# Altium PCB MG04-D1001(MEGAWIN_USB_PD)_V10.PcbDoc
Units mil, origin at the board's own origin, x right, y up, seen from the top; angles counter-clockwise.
Board outline 2047.24 x 1181.1 mil, 2 copper layers (Top Layer, Bottom Layer); 67 components, 68 nets, 243 pads, 62 vias.
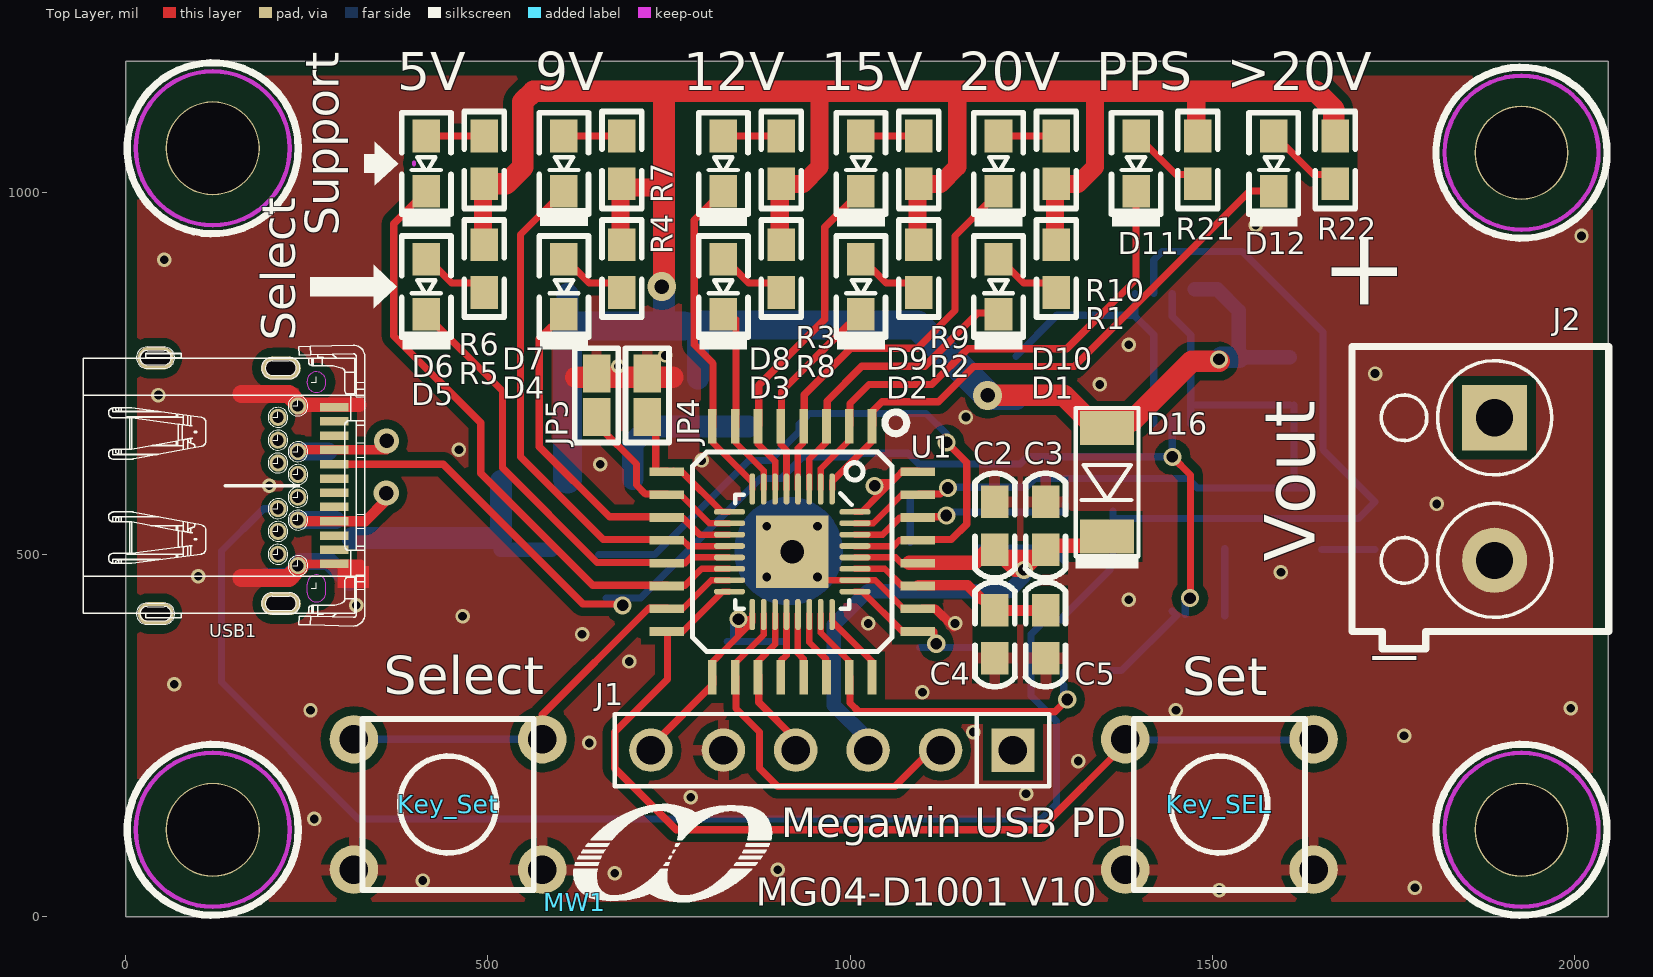
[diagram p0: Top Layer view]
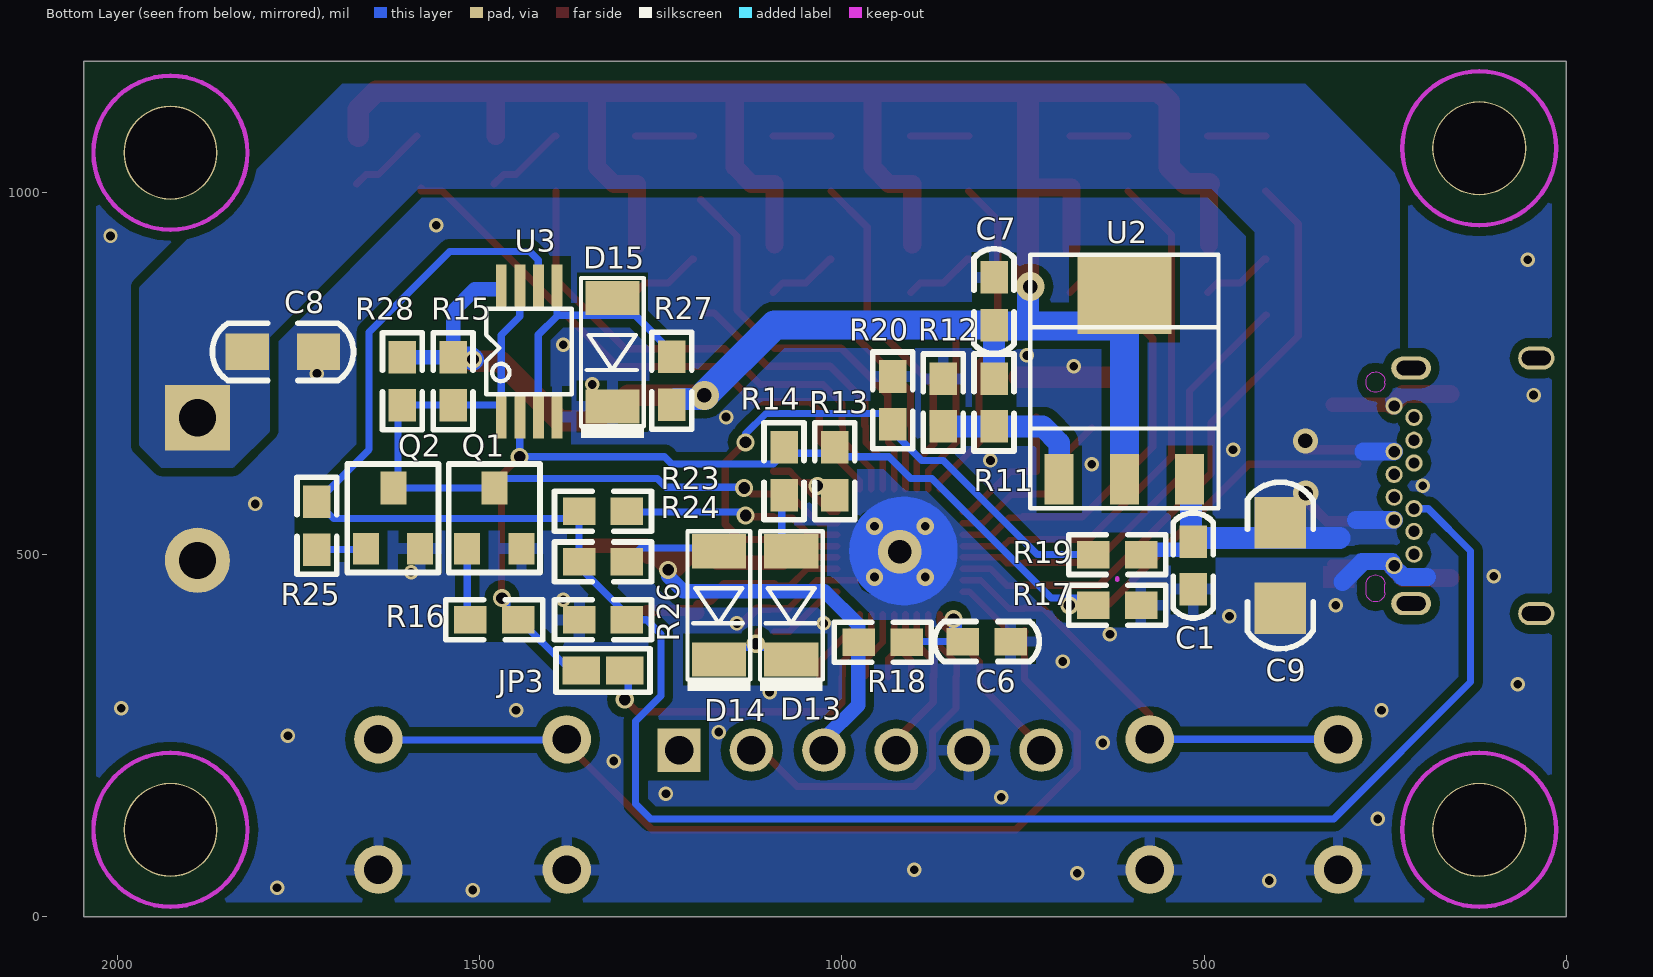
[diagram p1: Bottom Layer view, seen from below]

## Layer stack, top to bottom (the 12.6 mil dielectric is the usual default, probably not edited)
Top Layer: signal copper 1.4
Dielectric: dielectric 12.6, FR-4, Dk 4.8
Bottom Layer: signal copper 1.4

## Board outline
0,0 2047.24,0 2047.24,1181.1 0,1181.1

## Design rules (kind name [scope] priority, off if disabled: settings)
Clearance 15 [All] p1 off: gap=15
Clearance 12 [All] p2 off: gap=12
Clearance 6 [All] p3: gap=6
HoleSize [All] p1: absolutevalues=TRUE maxlimit=300 minlimit=1 maxpercent=80.000 minpercent=20.000
PolygonConnect J2 [(InComponent('J2'))] p1: connectstyle=Direct reliefconductorwidth=10 reliefentries=4 polygonreliefangle="90 Angle"
PolygonConnect C9 [(InComponent('C9'))] p2: connectstyle=Direct reliefconductorwidth=10 reliefentries=4 polygonreliefangle="90 Angle"
PolygonConnect C8 [(InComponent('C8'))] p3: connectstyle=Direct reliefconductorwidth=10 reliefentries=4 polygonreliefangle="90 Angle"
PolygonConnect USB_VBUS [(InComponent('USB1'))] p4: connectstyle=Direct reliefconductorwidth=10 reliefentries=4 polygonreliefangle="90 Angle"
PolygonConnect VIA [ISVIA] p5: connectstyle=Direct reliefconductorwidth=10 reliefentries=4 polygonreliefangle="90 Angle"
PolygonConnect ALL [All] p6: connectstyle=Relief reliefconductorwidth=15 reliefentries=4 polygonreliefangle="90 Angle"
RoomDefinition MG04-D1001(MEGAWIN_USB_PD)_V10 [InComponentClass('MG04-D1001(MEGAWIN_USB_PD)_V10')] p1: confinementstyle=ConfineIn formatcopy=TRUE lockcomponents=FALSE outline -110,-115 2100,-115 2100,1280 -110,1280
RoutingVias [All] p1: holewidth=16 width=28 viastyle="Through Hole" minholewidth=16 minwidth=25 maxholewidth=28 maxwidth=50
SilkscreenOverComponentPads [All] p1: minsilkscreentomaskgap=10
SolderMaskExpansion [All] p1: expansion=4
Width [All] p1: maxlimit=100 minlimit=6 preferedwidth=10
26 further rules are at their usual default settings.

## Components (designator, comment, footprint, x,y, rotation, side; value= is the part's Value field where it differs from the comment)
C1 "0.1uF" 0603C 515,485 r270 bottom
C2 "0.1uF" 0603C 1200,540 r90 top
C3 "10uF" 0603C 1270,540 r90 top
C4 "0.1uF" 0603C 1200,390 r270 top
C5 "4.7uF" 0603C 1270,390 r270 top
C6 "4.7uF" 0603C 800,380 r180 bottom
C7 "0.1uF" 0603C 790,850 r90 bottom
C8 "4.7uF 0805" 0805C 1772,780 r180 bottom
C9 "10uF 1206" 1206C 395,485 r270 bottom
D1 "LED_SC" 0603D 1205,870 r270 top (schematic designator LED1)
D2 "LED_SC" 0603D 1015,870 r270 top (schematic designator LED2)
D3 "LED_SC" 0603D 825,870 r270 top (schematic designator LED3)
D4 "LED_SC" 0603D 605,870 r270 top (schematic designator LED4)
D5 "LED_SC" 0603D 415,870 r270 top (schematic designator LED5)
D6 "LED_SC" 0603D 415,1040 r270 top (schematic designator LED6)
D7 "LED_SC" 0603D 605,1040 r270 top (schematic designator LED7)
D8 "LED_SC" 0603D 825,1040 r270 top (schematic designator LED8)
D9 "LED_SC" 0603D 1015,1040 r270 top (schematic designator LED9)
D10 "LED_SC" 0603D 1205,1040 r270 top (schematic designator LED10)
D11 "LED_SC" 0603D 1395,1040 r270 top
D12 "LED_SC" 0603D 1585,1040 r270 top
D13 "1N5817" D4148_SMD 1070,430 r270 bottom
D14 "1N5817" D4148_SMD 1170,430 r270 bottom
D15 "-" D4148_SMD 1317,779.5 r270 bottom
D16 "-" D4148_SMD 1355,600 r270 top
J1 "CON6" PS6P254 1225,230 r180 top
J2 "PIN2_5.0A" PIN2_5.0A 1890,590.55 r90 top locked
JP3 "JUMPER_2" 0603J 1330,340 r0 bottom
JP4 "JUMPER_2" 0603J 720,720 r270 top
JP5 "JUMPER_2" 0603J 650,720 r270 top
Key_SEL "SW-PB" SW_T 1510,155 r270 top
Key_Set "SW-PB" SW_T 445,155 r270 top
MW1 "MW-A4" MEGAWIN_3.4_LOGO 620,20 r0 top
Q1 "NPN" SOT23 1480,550 r180 bottom
Q2 "NPN" SOT23 1620,550 r180 bottom
R1 "1K" 0603R 1285,895 r90 top
R2 "1K" 0603R 1095,895 r90 top
R3 "1K" 0603R 905,895 r90 top
R4 "1K" 0603R 685,895 r90 top
R5 "1K" 0603R 495,895 r90 top
R6 "1K" 0603R 495,1045 r270 top
R7 "1K" 0603R 685,1045 r270 top
R8 "1K" 0603R 905,1045 r270 top
R9 "1K" 0603R 1095,1045 r270 top
R10 "1K" 0603R 1285,1045 r270 top
R11 "220" 0603R 790,710 r270 bottom
R12 "360" 0603R 860,710 r90 bottom
R13 "200" 0603R 1010,615 r270 bottom
R14 "100" 0603R 1080,615 r270 bottom
R15 "5.1K" 0603R 1537,739.5 r90 bottom
R16 "20K" 0603R 1480,410 r0 bottom
R17 "5.1K" 0603R 620,430 r0 bottom
R18 "47K" 0603R 943.78,378.91 r0 bottom
R19 "51K" 0603R 620,500 r180 bottom
R20 "10K" 0603R 930,713 r90 bottom
R21 "1K" 0603R 1480,1045 r90 top
R22 "1K" 0603R 1670,1045 r90 top
R23 "200" 0603R 1330,560 r180 bottom
R24 "100" 0603R 1330,490 r180 bottom
R25 "20K" 0603R 1725,540 r270 bottom
R26 "5.1K" 0603R 1330,410 r180 bottom
R27 "10k" 0603R 1235,740 r90 bottom
R28 "4.7k" 0603R 1607,739.5 r270 bottom
U1 "MG82F6P32 _LQFP32(7X7) / QFN32(4X4)" QFP32_7X7_QFN32_4X4 920.15,504 r270 top
U2 "SOT223(DCY)" SOT223 700,604.09 r180 bottom
U3 "TLV1702(VSSOP8)" SO8_120P065 1432,780.5 r180 bottom
USB1 "TYPE-C1 母座" USB24_CF 237.68,595 r90 top

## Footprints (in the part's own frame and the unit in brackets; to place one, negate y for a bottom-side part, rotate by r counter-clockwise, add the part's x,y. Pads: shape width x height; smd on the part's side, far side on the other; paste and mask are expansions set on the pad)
0603C [mil]
  rect 45x38 smd: 1(-33,0) 2(33,0)
  silkscreen extent -72,-28 72,28
0603D [mil]
  rect 45x38 smd: 1(-38,0) 2(38,0)
  silkscreen extent -70,-34 87,34
0603J [mil]
  rect 52x38 smd: 1(-30,0) 2(30,0)
  silkscreen extent -65,-30 65,30
0603R [mil]
  rect 45x38 smd: 1(-33,0) 2(33,0)
  silkscreen extent -67,-28 67,28
0805C [mil]
  rect 60x50 smd: 1(-49.21,0) 2(49.21,0)
  silkscreen extent -97,-39 97,39
1206C [mm]
  rect 1.8x1.8 smd: 1(-1.5,0) 2(1.5,0)
  silkscreen extent -2.92,-1.15 2.92,1.16
D4148_SMD [mm]
  rect 1.2x1.9 smd: 1(-1.9,0) 2(1.9,0)
  silkscreen extent -2.6,-1.1 3,1.1
MEGAWIN_3.4_LOGO [mil]
  silkscreen extent -2,0 272,135
PIN2_5.0A [mil]
  rect 90x90 hole 51.18: 1(98.43,0)
  round 90 hole 51.18: 2(-98.43,0)
  silkscreen extent -220,-157 197,197
PS6P254 [mil]
  rect 60x60 hole 39.37: 1(0,0)
  round 60 hole 39.37: 2(100,0) 3(200,0) 4(300,0) 5(400,0) 6(500,0)
  silkscreen extent -50,-50 550,50
QFP32_7X7_QFN32_4X4 [mm]
  rect 1.219x0.305 smd: 1(-4.4,2.8) 2(-4.4,2) 3(-4.4,1.2) 4(-4.4,0.4) 5(-4.4,-0.4) 6(-4.4,-1.2) 7(-4.4,-2) 8(-4.4,-2.8) 17(4.4,-2.8) 18(4.4,-2) 19(4.4,-1.2) 20(4.4,-0.4) 21(4.4,0.4) 22(4.4,1.2) 23(4.4,2) 24(4.4,2.8)
  oval 1.1x0.2 smd: 1(-2.2,1.4) 2(-2.2,1) 3(-2.2,0.6) 4(-2.2,0.2) 5(-2.2,-0.2) 6(-2.2,-0.6) 7(-2.2,-1) 8(-2.2,-1.4) 17(2.2,-1.4) 18(2.2,-1) 19(2.2,-0.6) 20(2.2,-0.2) 21(2.2,0.2) 22(2.2,0.6) 23(2.2,1) 24(2.2,1.4)
  rect 0.305x1.219 smd: 9(-2.8,-4.4) 10(-2,-4.4) 11(-1.2,-4.4) 12(-0.4,-4.4) 13(0.4,-4.4) 14(1.2,-4.4) 15(2,-4.4) 16(2.8,-4.4) 25(2.8,4.4) 26(2,4.4) 27(1.2,4.4) 28(0.4,4.4) 29(-0.4,4.4) 30(-1.2,4.4) 31(-2,4.4) 32(-2.8,4.4)
  oval 0.2x1.1 smd: 9(-1.4,-2.2) 10(-1,-2.2) 11(-0.6,-2.2) 12(-0.2,-2.2) 13(0.2,-2.2) 14(0.6,-2.2) 15(1,-2.2) 16(1.4,-2.2) 25(1.4,2.2) 26(1,2.2) 27(0.6,2.2) 28(0.2,2.2) 29(-0.2,2.2) 30(-0.6,2.2) 31(-1,2.2) 32(-1.4,2.2)
  rect 2.54x2.54 smd: G(0,0)
  Top Layer lines w0.229: 2.8,-4.4 2.8,-4.375 2.8,-3.869 2.8,-3.841 1.4,-2.441 1.4,-2.2 ; 0.4,-4.4 0.4,-3.758 0.2,-3.558 0.2,-2.2 ; -1.2,-4.4 -1.2,-3.848 -0.6,-3.248 -0.6,-2.2 ; -2.8,-4.4 -2.8,-4.318 -2.8,-4.191 -2.8,-3.867 -1.4,-2.467 -1.4,-2.2 ; -0.406,-4.394 -0.406,-3.835 -0.2,-3.629 -0.2,-2.2 ; 2,-4.349 2,-3.841 1,-2.841 1,-2.2 ; 1.2,-4.349 1.2,-3.777 0.6,-3.177 0.6,-2.2 ; -2,-4.349 -2,-3.911 -1,-2.911 -1,-2.2 ; 4.4,-2.8 3.867,-2.8 3.329,-2.263 3.015,-1.948 2.682,-1.615 2.656,-1.589 2.467,-1.4 2.2,-1.4 ; -4.4,-2.8 -3.841,-2.8 -2.441,-1.4 -2.2,-1.4 ; 4.349,-2 3.911,-2 2.911,-1 2.2,-1 ; -4.349,-2 -3.841,-2 -2.841,-1 -2.2,-1 ; 4.4,-1.2 3.848,-1.2 3.248,-0.6 2.2,-0.6 ; -4.349,-1.2 -3.777,-1.2 -3.177,-0.6 -2.2,-0.6 ; 4.394,-0.406 3.835,-0.406 3.629,-0.2 2.2,-0.2 ; -4.4,-0.4 -3.758,-0.4 -3.558,-0.2 -2.2,-0.2 ; 2.2,0.2 3.558,0.2 3.758,0.4 4.4,0.4 ; -2.2,0.2 -3.629,0.2 -3.835,0.406 -4.394,0.406 ; 2.2,0.6 3.177,0.6 3.777,1.2 4.349,1.2 ; -2.2,0.6 -3.248,0.6 -3.848,1.2 -4.4,1.2 ; 2.2,1 2.841,1 3.841,2 4.349,2 ; -2.2,1 -2.911,1 -3.911,2 -4.349,2 ; 2.2,1.4 2.441,1.4 3.841,2.8 4.4,2.8 ; -2.2,1.4 -2.467,1.4 -3.867,2.8 -4.4,2.8 ; 1.4,2.2 1.4,2.467 2.8,3.867 2.8,4.4 ; 1,2.2 1,2.911 2,3.911 ; 0.6,2.2 0.6,3.248 1.2,3.848 1.2,4.4 ; 0.2,2.2 0.2,3.629 0.406,3.835 0.406,4.394 ; -0.2,2.2 -0.2,3.558 -0.4,3.758 -0.4,4.4 ; -0.6,2.2 -0.6,3.177 -1.2,3.777 -1.2,4.349 ; -1,2.2 -1,2.841 -2,3.841 -2,4.349 ; -1.4,2.2 -1.4,2.441 -1.649,2.69 -1.776,2.817 -2.081,3.122 -2.119,3.16 -2.144,3.186 -2.182,3.224 -2.221,3.262 -2.438,3.48 -2.525,3.567 -2.692,3.734 -2.718,3.759 -2.794,3.835 -2.8,3.841 -2.8,3.943 -2.8,4.4
  Top Layer lines w0.254: 2,3.911 2,4.881
  silkscreen extent -4.9,-3.5 3.5,4.01
SO8_120P065 [mil]
  rect 15x60 smd: 1(-38.39,-90) 2(-12.8,-90) 3(12.8,-90) 4(38.39,-90) 5(38.39,90) 6(12.8,90) 7(-12.8,90) 8(-38.39,90)
  silkscreen extent -59,-59 59,59
SOT23 [mil]
  rect 36x43.31 smd: 1(-37.5,-41.97) 2(37.5,-41.97)
  rect 36x46.06 smd: 3(0.5,41.97)
  silkscreen extent -63,-74 63,75
SOT223 [mil]
  rect 40x70 smd: 1(0,0) 2(90,0) 3(180,0)
  rect 129.92x110.24 smd: 2(90,255.91)
  silkscreen extent -40,-40 220,310
SW_T [mm]
  round 1.7 hole 1: 1(-2.286,3.302) 1(-2.286,-3.302) 2(2.286,3.302) 2(2.286,-3.302)
  silkscreen extent -3,-3 3,3
USB24_CF [mm]
  oval 0.813x1.27 hole 0.508 slot 1.016 at 90 deg: 10(-4.48,4.99) 10(4.48,4.99)
  oval 0.813x1.397 hole 0.508 slot 1.016 at 90 deg: 10(-4.13,0.6) 13(4.13,0.6)
  rect 0.3x1 smd: A1(2.76,-1.267) A2(2.26,-1.267) A3(1.75,-1.267) A4(1.26,-1.267) A5(0.76,-1.267) A6(0.25,-1.267) A7(-0.25,-1.267) A8(-0.74,-1.267) A9(-1.24,-1.267) A10(-1.75,-1.267) A11(-2.24,-1.267) A12(-2.74,-1.267)
  round 0.6 hole 0.4: B1(-2.8,0) B2(-2.4,0.7) B3(-1.6,0.7) B4(-1.2,0) B5(-0.8,0.7) B6(-0.4,0) B7(0.4,0) B8(0.8,0.7) B9(1.2,0) B10(1.6,0.7) B11(2.4,0.7) B12(2.8,0)
  Keep-Out Layer lines w0.02: 3.599,-0.975 3.675,-0.975 ; 3.602,-0.975 cw(c3.602,-0.65) 3.599,-0.325 3.675,-0.325 cw(c3.672,-0.65) 3.672,-0.975 ; -3.745,-0.325 ccw(c-3.745,-0.65) -3.745,-0.975 -3.445,-0.975 ccw(c-3.445,-0.65) -3.445,-0.325 -3.745,-0.325
  silkscreen extent -4.92,-2.35 4.93,7.53

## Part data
C1 C2 C3 C4 C5 C6 C7 C8 C9: library part CAP, "Capacitor"
D13 D14 D15 D16: library part DIODE, "Diode"
J1: "Connector"
J2: library part CON2, "Connector"
JP3 JP4 JP5: "Jumper"
MW1: library part MW_A4_1
Q1 Q2: "NPN Transistor"
R1 R2 R3 R4 R5 R6 R7 R8 R9 R10 R11 R12 R13 R14 R15 R16 R17 R18 R19 R20 R21 R22 R23 R24 R25 R26 R27 R28: library part RES1
U1: library part IC32_MG82FG5C64
U2: library part TO220_AOI
U3: library part IC8_TLV1702
USB1: library part "USB TYPE-C"

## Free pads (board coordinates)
  round 130 hole 125.98 unplated: 1(120,120) 1(120,1061.1) 1(1927.24,120) 1(1927.24,1055)

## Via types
v1: diameter 20, hole 12, Top Layer to Bottom Layer, tented both sides, 41 vias
v2: diameter 25, hole 16, Top Layer to Bottom Layer, tented both sides, 12 vias
v3: diameter 24, hole 12, Top Layer to Bottom Layer, tented both sides, 4 vias
v4: diameter 35, hole 20, Top Layer to Bottom Layer, tented both sides, 2 vias
v5: diameter 40, hole 20, Top Layer to Bottom Layer, tented both sides, 2 vias
v6: diameter 60, hole 32, Top Layer to Bottom Layer, tented both sides, 1 vias

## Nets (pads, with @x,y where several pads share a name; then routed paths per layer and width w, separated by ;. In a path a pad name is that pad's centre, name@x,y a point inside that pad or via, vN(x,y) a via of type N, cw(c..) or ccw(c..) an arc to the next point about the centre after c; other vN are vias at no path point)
A2: USB1.A2
A3: USB1.A3
A6: USB1.A6
A7: USB1.A7
A8: USB1.A8
A10: USB1.A10
A11: USB1.A11
B2: USB1.B2
B3: USB1.B3
B6: USB1.B6
B7: USB1.B7
B8: USB1.B8
B10: USB1.B10
B11: USB1.B11
CC1: JP3.2 R13.1 R14.1 R16.1 R17.2 U3.2 USB1.A5 | length 1781.2
  Top Layer w10: USB1.A5 438.15,624.92 631.07,432 v2@688,432 ; v2(1445,635) 1469.98,610.02 v2@1469.98,440
  Bottom Layer w10: R17.2@663,440 711,440 876,605 905,605 935,635 1010,635 1015,640 1080,640 1095,625 1235,625 1245,635 v2@1444.8,635 ; JP3.2 1375,340 1451,416 R16.1@1445,422 ; U3.2 v2@1444.8,635 ; v2@1449,635 v2(1445,635) v2@1444.8,635 ; R16.1@1462.85,417.56 1462.85,438.76 v2@1468.96,444.87
  other v2: 686,430 1469.43,440
CC2: R23.1 R24.1 R25.1 R26.2 U3.6 USB1.B5 | length 2973.8
  Bottom Layer w10: USB1.B5 190.43,563.5 132,505.07 132,324 321,135 1264,135 1285,156 1285,270 1250,305 1250,390 1270,410 R26.2@1290,410 ; R26.2 R26.2@1290,410 ; R23.1 R23.1@1363,550 ; U3.6@1419.2,860.5 U3.6 1419.2,906.7 1431,918.5 1541.5,918.5 1653,807 1653,645 R25.1 1702,550 R23.1@1363,550 ; R26.2@1290,410 1359,479 1359,494 1363,498 R23.1@1363,550
KEY_SEL: Key_Set.1 U1.15 | length 538.5
  Top Layer w10: Key_Set.1@560,245 Key_Set.1@567.5,252.5 ; Key_Set.1@575,245 575,279 722.26,426.26 U1.15@747.93,426.26
  Bottom Layer w10: Key_Set.1@315,245 Key_Set.1@575,245
KEY_SET: Key_SEL.1 U1.16 | length 1282.5
  Top Layer w10: U1.16@747.93,394.76 747.93,393.76 747.93,327.93 675,255 675,205 760,120 1262,120 Key_SEL.1@1386,244
  Bottom Layer w10: Key_SEL.1@1380,250 1386,244 1634,244 Key_SEL.1@1640,250
NetD1_1: D1.1 R1.1 | length 99.1
  Top Layer w10: D1.1 1207,908 1240,875 1272,875 R1.1
NetD2_1: D2.1 R2.1 | length 99.1
  Top Layer w10: D2.1 1017,908 1050,875 1082,875 R2.1
NetD3_1: D3.1 R3.1 | length 99.1
  Top Layer w10: D3.1 827,908 860,875 892,875 R3.1
NetD4_1: D4.1 R4.1 | length 99.1
  Top Layer w10: D4.1 607,908 640,875 672,875 R4.1
NetD5_1: D5.1 R5.1 | length 99.1
  Top Layer w10: D5.1 417,908 450,875 482,875 R5.1
NetD6_1: D6.1 R6.1 | length 80
  Top Layer w10: D6.1 R6.1
NetD7_1: D7.1 R7.1 | length 80
  Top Layer w10: D7.1 R7.1
NetD8_1: D8.1 R8.1 | length 80
  Top Layer w10: D8.1 R8.1
NetD9_1: D9.1 R9.1 | length 80
  Top Layer w10: D9.1 R9.1
NetD10_1: D10.1 R10.1 | length 80
  Top Layer w10: D10.1 R10.1
NetD11_1: D11.1 R21.1 | length 112.3
  Top Layer w10: D11.1 1397,1078 1450,1025 1467,1025 R21.1
NetD12_1: D12.1 R22.1 | length 110.3
  Top Layer w10: D12.1@1587,1078 1640,1025 1657,1025 R22.1
NetD13_1: D13.1 R14.2 | length 59.8
  Bottom Layer w10: D13.1@1083,517 R14.2@1083,576.83
NetD14_1: D14.1 R24.2 | length 130.7
  Bottom Layer w10: D14.1@1174.2,509 1278,509 R24.2
NetD15_1: D15.1 R27.2 U3.3 U3.5 | length 378.6
  Bottom Layer w10: R27.2@1229.03,773.97 1285.56,830.5 1393.61,830.5 ; U3.5@1393.61,860.5 1393.61,830.5 ; U3.3@1419.2,680.5 U3.3 1419.2,803.5 1393.61,829.09 1393.61,830.5
NetQ1_1: Q1.1 R16.2 | length 97.1
  Bottom Layer w10: R16.2@1517.5,415.5 Q1.1 Q1.1@1517.5,503.5
NetQ2_1: Q2.1 R25.2 | length 73.5
  Bottom Layer w10: Q2.1@1651.47,507 R25.2
NetR11_2: R11.2 R12.1 U2.1 | length 219.5
  Bottom Layer w30: U2.1 700,654.09 722.91,677 R11.2 R12.1
P01: U1.22
P02: JP3.1 U1.23 | length 376.8
  Top Layer w10: U1.23@999.89,331.77 999.89,295.11 1012,283 1283,283 v2(1300,300)
  Bottom Layer w10: v2@1295,300 1295,320 ; JP3.1@1295,330 JP3.1@1295,338
P05: U1.24
P30: JP4.2 U1.9 | length 91.5
  Top Layer w10: JP4.2@731.69,690 731.69,615.24 U1.9@747.93,615.24 ; U1.9@736.93,615 U1.9@736.93,615.24 ; U1.9@756.15,615 U1.9@756.15,615.24
P31: JP5.2 U1.10 | length 147.6
  Top Layer w10: JP5.2@655,675 705,625 705,596.15 717.41,583.74 U1.10@747.93,583.74
P60: U1.21
P61: U1.20
RST: C6.1 J1.6 R18.1 U1.17 | length 318.5
  Top Layer w9: 846,391 v2(846,411) U1.17@864,411
  Top Layer w10: J1.6@729.04,222.89 J1.6@729.04,239.04 ; J1.6@729.04,249.04 J1.6@729.04,239.04 ; U1.17@810.92,331.77 810.92,320.92 J1.6@729.04,239.04
  Bottom Layer w10: C6.1@830,380 C6.1 C6.1@839,380 ; v2@839,412 C6.1@839,380 ; C6.1@847,396 v2@847,412 ; R18.1@909.69,380 C6.1@839,380
RXD1: Q1.3 Q2.3 R15.1 R28.2 U1.31 U3.1 U3.7 | length 985.1
  Top Layer w10: U1.31@1094.38,583.74 1124.89,583.74 v2@1134.08,592.92
  Bottom Layer w10: v2@1134.08,592.92 1242.92,592.92 1255,605 1466.47,605 Q1.3 ; U3.7@1444.8,860.5 1444.8,828.7 1470.39,803.11 U3.1 U3.1@1470.39,680.5 ; U3.1@1476.39,706.5 R15.1 R28.2 ; Q1.3@1480,591.97 Q2.3@1613,591.97 ; R28.2@1613,706.5 Q2.3@1613,591.97 ; Q2.3@1630,591.97 Q2.3 Q2.3@1613,591.97
  other v2: 1135,592
SCL: J1.2 U1.18 | length 401.2
  Top Layer w10: U1.18@842.41,331.77 842.41,287.59 875,255 875,205 900,180 1061.93,180 J1.2@1106.93,225
SDA: J1.4 U1.19 | length 170.4
  Top Layer w10: 873.91,306.09 U1.19@873.91,330.77 ; U1.19@873.91,333.77 U1.19@873.91,330.77 ; J1.4@910,230 J1.4 ; J1.4@926.93,225 926.93,243.07 873.91,296.09 U1.19@873.91,330.77
SEL_LED5: D5.2 U1.13 | length 537.6
  Top Layer w10: D5.2@414,831 415,831 520,726 520,620 650.75,489.25 U1.13@747.93,489.25
SEL_LED9: D4.2 U1.11 | length 416.1
  Top Layer w10: D4.2 571,798 571,649 667.76,552.24 U1.11@749.93,552.24
SEL_LED12: D3.2 U1.7 | length 148.4
  Top Layer w10: U1.7@842.41,676.23 D3.2@842.41,824.59
SEL_LED15: D2.2 U1.5 | length 177.4
  Top Layer w10: U1.5@905.41,678.23 905.41,725.41 D2.2@997.5,817.5
SEL_LED20: D1.2 U1.3 | length 309.3
  Top Layer w10: U1.3@968.4,678.23 968.4,712.24 1016.15,760 1103,760 1176.5,833.5 D1.2@1193.5,833.5
SUP_HIGHER: D12.2 U1.1 | length 699.5
  Top Layer w10: U1.1@1031.39,678.23 1031.39,698.39 1044,711 1122,711 1170.67,759.67 1309.67,759.67 1552,1002 1581,1002 D12.2@1581,1006
SUP_LED5: D6.2 U1.14 | length 779.9
  Top Layer w10: D6.2 370,957 370,802 490,682 490,612.5 644.74,457.76 U1.14@747.93,457.76
SUP_LED9: D7.2 U1.12 | length 642.1
  Top Layer w10: D7.2 545,942 545,635 659.25,520.75 U1.12@747.93,520.75
SUP_LED12: D8.2 U1.8 | length 353.1
  Top Layer w10: U1.8@810.92,676.23 810.92,764.08 785,790 785,962 D8.2
SUP_LED15: D9.2 U1.6 | length 382.2
  Top Layer w10: U1.6@873.91,678.23 873.91,733.91 965,825 965,952 D9.2
SUP_LED20: D10.2 U1.4 | length 472.5
  Top Layer w10: U1.4@936.9,678.23 936.9,720.75 1001.15,785 1093,785 1145,837 1145,940 D10.2@1195,990
SUP_PPS: D11.2 U1.2 | length 618.6
  Top Layer w10: U1.2@999.89,678.23 999.89,708.74 1026.15,735 1113,735 1162.42,784.42 1299.42,784.42 1395,880 D11.2
TX_EN: D13.2 D14.2 U1.25 | length 95.8
  Top Layer w10: v2@1116,372 U1.25@1116,393.76
  Bottom Layer w10: D13.2@1096,371.8 D14.2@1170,371.8
  other v2: 1119,377
TXD1: R13.2 U1.32 | length 45.1
  Top Layer w9: v2@1034,600 1057.16,600
  Top Layer w10: U1.32@1072.39,615.24 U1.32@1094.38,615.24
  other v2: 1034,595
TXD1_1: R23.2 U1.30 | length 219.3
  Top Layer w10: U1.30@1094.38,552.24 v2@1139.24,552.24
  Bottom Layer w10: v2@1133,559 1296,559 R23.2 R23.2@1297,570
  other v2: 1133,554
USB_VBUS: C1.1 C8.1 C9.1 J2.1 R19.2 U2.3 USB1.A4 USB1.A9 USB1.B4 USB1.B9 | length 717.1
  Top Layer w13: USB1.B9@237.68,644.61 USB1.A4 v4@360,644.61
  Top Layer w15: USB1.B4@237.68,546.18 USB1.A9 330.61,546.18 359.43,575 v4(359.43,585)
  Bottom Layer w10: USB1.B4 USB1.B4@237.94,548.02
  Bottom Layer w20: C1.1@518,507 R19.2@588,507
  Bottom Layer w25: USB1.B4 290,547.76 ; USB1.B9 280,642.24
  Bottom Layer w30: 313,523 C1.1@518,523 ; C1.1@518,521 C1.1@518,523 ; U2.3@518,602.09 C1.1@518,523
  other v4: 360,657
VBUS_VOLT: R19.1 R20.1 U1.29 | length 783.2
  Top Layer w10: U1.29@1094.38,520.75 1139.75,520.75 1161,542 1161,627.23 v2(1133.23,655)
  Bottom Layer w10: R19.1 730,500 860,630 890,630 930,670 R20.1 R20.1@940,690 ; R20.1@945,695 1105,695 1133.23,666.77 v2(1133.23,655)
VCAP: C4.1 C5.1 U1.27 | length 188.4
  Top Layer w15: U1.27@1094.38,457.76 1162.24,457.76 1182.1,437.9 C4.1@1186.1,437.9 ; C4.1@1198.5,429.65 1198.5,421.5 C4.1@1200,420 ; C4.1 C5.1
  Top Layer w20: C4.1@1200,420 C4.1@1208.15,420
VDD: C7.1 D16.1 R1.2 R2.2 R3.2 R4.2 R5.2 R6.2 R7.2 R8.2 R9.2 R10.2 R11.1 R15.2 R21.2 R22.2 R27.1 R28.1 U2.2 U3.8 | length 4257.4
  Top Layer w25: R5.2@493,928 R6.2@493,1012 ; R4.2@683,923 683,1007 733,1007 ; R3.2@903,928 903,1012 R8.2 935,1012 958,1035 958,1140 ; R2.2@1093,928 1093,1012 R9.2 1125,1012 1148,1035 1148,1140 ; R1.2@1283,928 1283,1012 R10.2 1315,1012 1338,1035 1338,1140 ; R21.2@1478,1078 1478,1140
  Top Layer w30: R6.2@493,1012 R6.2 525,1012 548,1035 548,1125 563,1140 958,1140 1148,1140 1338,1140 1478,1140 1643,1140 1668,1115 R22.2@1668,1078 ; v5@743,870 743,1135 ; v5(1190,720) 1295,720 1330,685 1390,685 1472,767 v2@1509.44,767
  Bottom Layer w20: U3.8@1476,866.5 1506.93,866.5 1537,836.43 R15.2 R28.1
  Bottom Layer w30: U2.2@610,816 U2.2@610,860 ; 743,816 v5@743,870 ; R11.1 C7.1 ; v5@1195,715 R27.1@1230,715 ; v2(1509.44,769.5) 1512.44,772.5 R15.2
  Bottom Layer w40: U2.2@610,604.09 610,816 743,816 770.5,816 ; C7.1 1093,817 v5(1190,720)
  other v5: 740,870
VDD_U1: C2.1 C3.1 D16.2 J1.3 R18.2 U1.28 | length 863.4
  Top Layer w10: U1.28@1092.38,489.25 U1.28@1094.38,489.25
  Top Layer w20: U1.28@1082,489 1172,489 1190,507 C2.1 C2.1@1210,497 ; C2.1@1200,497 C2.1@1210,497 ; C3.1@1268,497 C3.1@1258,497 ; C3.1 1268,507 C3.1@1258,497 ; C3.1@1270,512 D16.2@1353.2,512 ; C2.1@1210,497 C3.1@1258,497 ; C2.1@1210,497 1228,479 v2(1240,479) C3.1@1258,497
  Bottom Layer w20: J1.3 1025,245 977.78,292.22 977.78,403.03 1024.14,449.4 1219.4,449.4 1240,470 v2(1240,479)
VSS: C1.2 C2.2 C3.2 C4.2 C5.2 C6.2 C7.2 C8.2 C9.2 D15.2 J1.5 J2.2 JP4.1 JP5.1 Key_SEL.2 Key_Set.2 Q1.2 Q2.2 R12.2 R17.1 R20.2 R26.1 U1.26 U1.G U3.4 USB1.A1 USB1.A12 USB1.B1 USB1.B12 | length 1016.9
  Top Layer w9: U1.G@947.29,464.63 U1.26@1006.77,464.63
  Top Layer w10: U1.G@956.15,470 U1.G@960.52,465.63
  Top Layer w12: USB1.B1@237.68,487 324.27,487 ; U1.26@1100,425.26 1117.84,425.26 v1@1143.1,400
  Top Layer w20: USB1.B12@236,707 322.59,707
  Top Layer w25: 160,468 225,468 USB1.B1@240.68,484 ; 160,722 225,722 USB1.B12@240.68,706
  Top Layer w30: 621.42,745 755,745
  Bottom Layer w23: USB1.B1@240.41,490.5 282.5,490.5
  Bottom Layer w25: 192,469 224.91,469 USB1.B1@239.68,483.76 ; 282.5,488.5 309,462
  Bottom Layer w60: 960,505 ccw(c915,505) 960,505
  other v1: 1510,36.89 1780,40 410,50 675,60 900,65 260,135 780,165 1243.02,170 1315,215 640,240 1765,250 1170,255 255,285 1450,285 1995,288 1100,310 67,321 695,352.44 630,390 1025,405 1145,405 465,415 318.15,430 1385,437.56 100,470.3 1595,475.51 1810,570 198,595 655,625 795,630 460,645 1160,690 45,720.3 1345,735 1725,750 680,760 745,775 1385,790 53,907 2010,940 1560,955
  other v3: 885.15,469 955.15,469 885.15,539 955.15,539
  other v6: 920.15,504
pads on no net: J1.1 USB1.10 USB1.13

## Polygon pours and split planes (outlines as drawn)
VSS on Bottom Layer "Bottom Layer-No Net" (solid, remove dead copper, pour order 1001): 20,20 2020,20 2030,20 2030,1160 20,1160
USB_VBUS on Bottom Layer "TopLayer-No Net" (solid, pour order 1000): 1840,620 1790,670 1790,800 1585,1005 490,1005 430,945 430,512 230,512 230,1020 360,1150 1690,1150 1970,870 1970,650 1940,620
VSS on Top Layer "Bottom Layer-No Net" (solid, remove dead copper, pour order 1000): 15.5,21 2015.5,21 2025.5,21 2025.5,1161 15.5,1161

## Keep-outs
Top Layer:
  lines w6: 398,1039 398,1041.5
Bottom Layer:
  lines w6: 620,465 620,467.5
Keep-Out Layer:
  circle w6: c120,1061.1 r106.3
  circle w6: c1927.24,1055 r106.3
  circle w6: c1927.24,120 r106.3
  circle w6: c120,120 r106.3

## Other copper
Top Layer:
  rectangle net VSS: 292,454 336,484

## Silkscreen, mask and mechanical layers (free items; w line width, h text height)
Top Overlay:
  circle w10: c1927.24,120 r118.11
  circle w10: c1927.24,1055 r118.11
  circle w10: c120,1061.1 r118.11
  circle w10: c120,120 r118.11
  region: 374,870 342,900 342,883 255,883 255,857 342,857 342,840
  region: 376,1040 344,1070 344,1053 329,1053 329,1027 344,1027 344,1010
  text "5V" at 375,1124 h90
  text "9V" at 565,1124 h90
  text "12V" at 770,1124 h90
  text "15V" at 960,1124 h90
  text "20V" at 1150,1124 h90
  text "PPS" at 1340,1124 h90
  text ">20V" at 1520,1124 h90
  text "Support" at 310,940 h80 r90
  text "+" at 1790,830 h180 r90
  text "Select" at 250,795 h80 r90
  text "Vout" at 1665,490 h120 r90
  text "Select" at 356,290 h90
  text "Set" at 1458.75,288.75 h90
  text "-" at 1710,245 h290
  text "Megawin USB PD" at 905,110 h41
  text "MG04-D1001 V10" at 870,15 h39
Mechanical 1:
  the board outline again, w8.88

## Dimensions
2047.24,0 to 0,0 on Top Overlay
1907.24,0 to 1907.24,1181.1 on Top Overlay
